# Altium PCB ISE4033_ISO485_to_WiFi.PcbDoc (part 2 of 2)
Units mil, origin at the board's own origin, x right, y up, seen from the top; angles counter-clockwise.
Board outline 4100 x 3450 mil, 4 copper layers (Top Layer, Signal Layer 1, Signal Layer 2, Bottom Layer), stack 52.6 mil thick; 125 components, 68 nets, 339 pads, 551 vias.
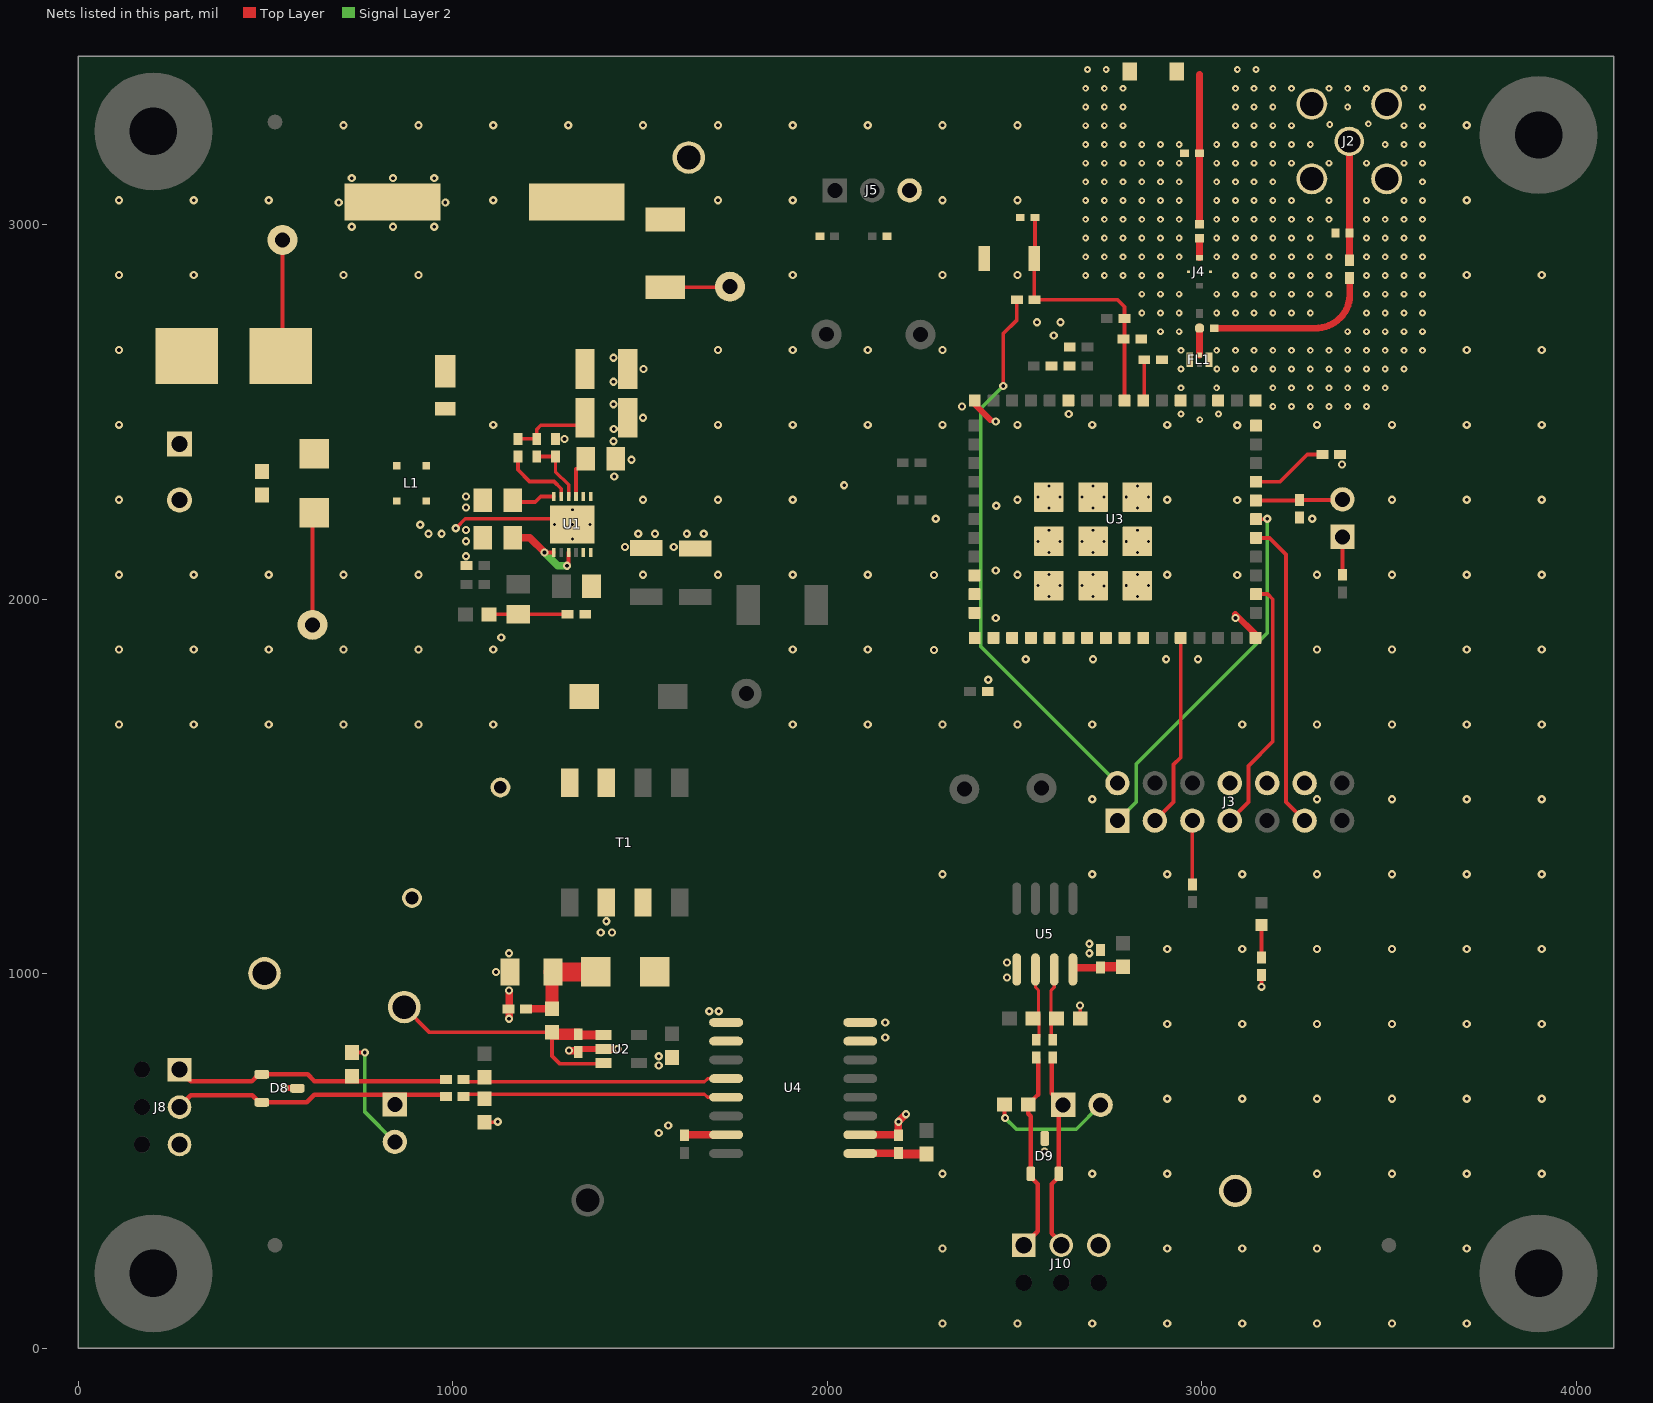
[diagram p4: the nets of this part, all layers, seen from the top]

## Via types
v1: diameter 22, hole 10, Top Layer to Bottom Layer, tented both sides, 276 vias
v2: diameter 18, hole 8, Top Layer to Bottom Layer, tented both sides, 233 vias
v3: diameter 19.68, hole 7.87, Top Layer to Bottom Layer, 41 vias
v4: diameter 22, hole 10, Top Layer to Bottom Layer, 1 vias

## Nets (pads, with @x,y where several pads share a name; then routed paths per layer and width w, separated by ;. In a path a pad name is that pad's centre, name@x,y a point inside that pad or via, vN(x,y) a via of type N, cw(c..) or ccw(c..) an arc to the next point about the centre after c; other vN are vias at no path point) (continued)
GND: C2.2 C3.2 C4.2 C5.2 C6.2 C10.2 C11.2 C12.2 C14.2 C18.1 C18.2 C19.2 C20.2 C21.2 C22.2 C23.1 C25.1 D4.2 D6.2 D7.2 D9.3 E1.1 E1.2 FL1.2 FL1.4 J2.2 J2.3 J2.4 J2.5 J3.8 J3.10 J3.12 J4.3 J4.4 J5.3 J10.3 L1.4 L3.1 L4.2 R7.1 R9.1 R18.1 R21.1 R22.1 R23.1 R24.1 R34.1 S1.2 TP5.1 TP6.1 U1.1 U1.2 U1.13 U3.1 U3.2 U3.16 U3.27 U3.28 U3.30 U3.32 U3.38 U3.43 U3.55 U3.56 U3.57 U3.58 U3.59 U3.60 U3.61 U3.62 U3.63 U4.2 U4.7 U4.8 U5.5 | length 1117.1
  Top Layer w10: v4(1008,2190) 1033,2215 1304,2215 v3(1319,2200) ; C23.1@2183.62,570 C23.1@2190,563.62 ; U3.43@2393.92,2521.08 U3.43@2393.92,2530.96 ; v1(2675,915) 2675.5,914.5 R34.1@2675.5,880 ; 2994.51,3402 2997.51,3405 ; 2995.9,3394.39 2996.51,3395 ; U3.16@3143.92,1897.1 U3.16@3143.92,1906.08 ; v1(3160,965) R21.1@3160,996.38
  Top Layer w17: U3.43@2393.92,2521.08 2435,2480 ; v1@3090,1960 U3.16@3143.92,1906.08
  Top Layer w18: L4.2@2994.12,3001.7 2994.12,3396.61 ; 2994.12,3401.61 2994.51,3402
  Top Layer w20: U4.2@2088.13,570 C23.1@2183.62,570 ; C23.1@2190,568.62 v1(2190,605) v1(2210,625)
  other v1: 2308,66 2508,66 2708,66 2908,66 3108,66 3308,66 3508,66 3708,66 2308,266 2908,266 3108,266 3308,266 3708,266 2308,466 2708,466 2908,466 3308,466 3508,466 3708,466 3908,466 2580,525 2908,666 3108,666 3308,666 3508,666 3708,666 3908,666 2155,830 2908,866 3108,866 3308,866 3508,866 3708,866 3908,866 2155,870 2480,990 2480,1030 2700,1055 2908,1066 3108,1066 3308,1066 3508,1066 3708,1066 3908,1066 2700,1080 2308,1266 2708,1266 2908,1266 3108,1266 3308,1266 3508,1266 3708,1266 3908,1266 2708,1466 3308,1466 3508,1466 3708,1466 3908,1466 108,1666 308,1666 508,1666 708,1666 908,1666 1108,1666 1908,1666 2108,1666 2308,1666 2508,1666 2708,1666 3108,1666 3308,1666 3508,1666 3708,1666 3908,1666 2430,1785 2530,1840 2710,1840 2905,1840 2990,1840 2285,1865 108,1866 308,1866 508,1866 708,1866 908,1866 1108,1866 1908,1866 2108,1866 3308,1866 3508,1866 3708,1866 3908,1866 1129,1898 2450,1950 3090,1950 2285,2065 3095,2065 108,2066 308,2066 508,2066 708,2066 908,2066 1508,2066 1708,2066 1908,2066 2108,2066 2508,2066 2908,2066 3308,2066 3508,2066 3708,2066 3908,2066 2450,2077 1035,2115 1460,2140 1590,2140 1035,2155 935,2175 970,2175 1495,2175 1540,2175 1625,2175 1670,2175 1035,2185 913,2199 2290,2215 3295,2215 1035,2245 2451,2250 3095,2265 108,2266 1508,2266 1708,2266 1908,2266 2508,2266 2908,2266 3508,2266 3708,2266 3908,2266 1035,2275 2045,2305 1431,2328 3375,2360 1477,2373 1429,2422 1298,2428 1430,2455 3095,2465 108,2466 1108,2466 1708,2466 1908,2466 2108,2466 2308,2466 2508,2466 2708,2466 2908,2466 3308,2466 3508,2466 3708,2466 3908,2466 2450,2475 1508,2485 2645,2495 2360,2515 1429,2521 1429,2581 1509,2615 1429,2645 108,2666 1708,2666 1908,2666 2108,2666 2308,2666 3708,2666 3908,2666 2605,2705 2560,2740 2623,2740 108,2866 308,2866 708,2866 908,2866 1908,2866 2308,2866 2508,2866 3708,2866 3908,2866 730,2995 840,2995 950,2995 695,3060 980,3060 108,3066 308,3066 508,3066 1108,3066 1708,3066 1908,3066 2308,3066 2508,3066 3708,3066 730,3125 840,3125 950,3125 708,3266 908,3266 1108,3266 1308,3266 1508,3266 1708,3266 1908,3266 2108,3266 2308,3266 2508,3266 3708,3266
  other v2: 2995,2480 2945,2495 3045,2495 3190,2515 3240,2515 3290,2515 3340,2515 3390,2515 3440,2515 2945,2565 3040,2565 3190,2565 3240,2565 3290,2565 3340,2565 3390,2565 3440,2565 3490,2565 2945,2615 3040.26,2615 3090,2615 3140,2615 3190,2615 3240,2615 3290,2615 3340,2615 3390,2615 3440,2615 3490,2615 3540,2615 2945,2665 3040,2665 3090,2665 3140,2665 3190,2665 3240,2665 3290,2665 3340,2665 3390,2665 3440,2665 3490,2665 3540,2665 3590,2665 2890,2715 2940,2715 3390,2715 3440,2715 3490,2715 3540,2715 3590,2715 2840,2765 2890,2765 2940,2765 3040,2765 3090,2765 3140,2765 3190,2765 3240,2765 3290,2765 3440,2765 3490,2765 3540,2765 3590,2765 2840,2815 2890,2815 2940,2815 3040,2815 3090,2815 3140,2815 3190,2815 3240,2815 3290,2815 3340,2815 3440,2815 3490,2815 3540,2815 3590,2815 2690,2865 2740,2865 2790,2865 2840,2865 2890,2865 3090,2865 3140,2865 3190,2865 3240,2865 3290,2865 3340,2865 3440,2865 3490,2865 3540,2865 3590,2865 2690,2915 2740,2915 2790,2915 2840,2915 2890,2915 2940,2915 3040,2915 3090,2915 3140,2915 3190,2915 3240,2915 3290,2915 3340,2915 3440,2915 3490,2915 3540,2915 3590,2915 2690,2965 2740,2965 2790,2965 2840,2965 2890,2965 2940,2965 3040,2965 3090,2965 3140,2965 3190,2965 3240,2965 3290,2965 3440,2965 3490,2965 3540,2965 3590,2965 2690,3015 2740,3015 2790,3015 2840,3015 2890,3015 2940,3015 3040,3015 3090,3015 3140,3015 3190,3015 3240,3015 3290,3015 3340,3015 3440,3015 3490,3015 3540,3015 3590,3015 2690,3065 2740,3065 2790,3065 2840,3065 2890,3065 2940,3065 3040,3065 3090,3065 3140,3065 3190,3065 3240,3065 3340,3065 3440,3065 3540,3065 3590,3065 2690,3115 2740,3115 2790,3115 2840,3115 2890,3115 2940,3115 3040,3115 3090,3115 3140,3115 3190,3115 3590,3115 2690,3165 2740,3165 2790,3165 2840,3165 2890,3165 2940,3165 3040,3165 3090,3165 3140,3165 3190,3165 3240,3165 3340,3165 3440,3165 3540,3165 3590,3165 2690,3215 2740,3215 2790,3215 2840,3215 2890,3215 2940,3215 3040,3215 3090,3215 3140,3215 3190,3215 3240,3215 3290,3215 3490,3215 3540,3215 3590,3215 2690,3265 2740,3265 2790,3265 3090,3265 3140,3265 3190,3265 3240,3265 3540,3265 3590,3265 3342,3268 3445,3270 2690,3315 2740,3315 2790,3315 3090,3315 3140,3315 3190,3315 3390,3315 3590,3315 2690,3365 2740,3365 2790,3365 3090,3365 3140,3365 3190,3365 3240,3365 3340,3365 3390,3365 3440,3365 3540,3365 3590,3365 2695,3415 2745,3415 3095,3415 3145,3415
  other v3: 2591.76,2007.34 2709.87,2007.34 2827.98,2007.34 2739.39,2035.88 2562.23,2036.87 2621.28,2036.87 2680.34,2036.87 2798.45,2036.87 2857.5,2036.87 2591.76,2066.39 2709.87,2066.39 2827.98,2066.39 2591.76,2125.45 2709.87,2125.45 2827.98,2125.45 2739.39,2153.99 2562.23,2154.98 2621.28,2154.98 2680.34,2154.98 2798.45,2154.98 2857.5,2154.98 1319,2160.63 2591.76,2184.5 2709.87,2184.5 2827.98,2184.5 1271.76,2200 1366.24,2200 1319,2239.37 2591.76,2243.56 2709.87,2243.56 2827.98,2243.56 2562.23,2273.09 2621.28,2273.09 2680.34,2273.09 2739.39,2273.09 2798.45,2273.09 2857.5,2273.09 2591.76,2302.61 2709.87,2302.61 2827.98,2302.61
GPIO7: U3.52
GPIO8: U3.53
GPIO9: U3.54
GPIO10: U3.3
GPIO11: U3.4
GPIO12: U3.9
GPIO13: U3.10
GPIO14: U3.5
GPIO15: U3.6
GPIO16: U3.7
GPIO17: U3.8
IN1: F1.2 J1.1
IN1_F: C1.1 D1.2 F1.1 L1.2 TP1.1 | length 311.9
  Top Layer w10: F1.1@540.49,2650 545,2654.51 TP1.1@545,2960
IN1_FL: D2.2 L1.1
IN2: C1.2 D1.1 J1.2 L1.3 TP4.1 | length 301.3
  Top Layer w10: TP4.1@625,1932 625,2226.26 D1.1@630,2231.26
ISO485_N: R30.2 R35.1 U4.13 | length 703.3
  Top Layer w8.5: R35.1@1030,678.25 1672.09,678.25 1680.34,670 U4.13@1729.87,670
ISO485_OUT_N: D8.2 J7.1 J8.2 R35.2 | length 743.2
  Top Layer w12: J8.2@270,644 270,645.5 300,675.5 464.5,675.5 483.4,656.6 D8.2@489.76,656.6 610.1,656.6 630,676.5 976.88,676.5 R35.2@981.38,672
ISO485_OUT_P: D8.1 J8.1 R25.2 R29.1 | length 742.4
  Top Layer w12: J8.1@270,744 270,742.5 300,712.5 462.5,712.5 481.4,731.4 D8.1@489.76,731.4 612.1,731.4 630,713.5 976.88,713.5 R25.2@981.38,718
ISO485_P: R25.1 R28.1 U4.12 | length 703.3
  Top Layer w8.5: R25.1@1030,711.75 1672.09,711.75 1680.34,720 U4.12@1729.87,720
ISO_GND: C6.1 C7.2 C15.2 C16.2 C24.1 D8.3 J8.3 R2.1 R30.1 T1.7 TP11.1 U2.2 U4.9 U4.10 U4.15 | length 388.4
  Top Layer w10: D8.3@583.24,695 D8.3@584.24,694 ; R30.1@1085,603.5 1118.5,603.5 v1(1120,605) ; C24.1@1619,568.62 C24.1@1620.38,570
  Top Layer w15: v1(550,695) D8.3@583.24,695 ; C16.2@1330,795 1334,799 U2.2@1402.6,799
  Top Layer w20: v1(1150,880) v1(1150,955) ; v1(1310,795) C16.2@1330,795 ; U2.2@1402.6,799 v1(1440,799) ; C24.1@1620.38,570 U4.15@1729.87,570
  other v1: 1550,575 1575,595 1550,755 1550,780 1685,900 1710,900 1115.51,1005 1150,1055 1395,1110 1425,1110 1410,1140
J4-2: J4.2 L4.1 | length 51.9
  Top Layer w18: J4.2@2994,2912.4 L4.1@2994,2964.3
LDO_IN: C16.1 R10.2 TP12.1 U2.1 U2.3 | length 773.5
  Top Layer w10: TP12.1@870,911 937.5,843.5 R10.2@1265,843.5 ; R10.2@1269.88,838.62 R10.2@1265,843.5 ; C16.1@1335,838.62 C16.1@1337.22,836.4 ; U2.3@1402.6,761.6 1401,760 1285,760 1265,780 R10.2@1265,843.5
  Top Layer w25: C16.1@1337.22,836.4 U2.1@1402.6,836.4
  Top Layer w30: R10.2@1269.88,838.62 C16.1@1335,838.62
NetC23_2: C23.2 R27.1 U4.1 | length 178.6
  Top Layer w10: C23.2@2188.62,520 C23.2@2190,521.38 C23.2@2192.87,518.5
  Top Layer w20: U4.1@2088.13,520 C23.2@2188.62,520
  Top Layer w25: C23.2@2192.87,518.5 R27.1@2265,518.5
NetC25_2: C25.2 R31.1 U5.8 | length 136.9
  Top Layer w10: U5.8@2656,1011.51 U5.8@2660.87,1016.38 ; C25.2@2730,1016.38 C25.2@2732.13,1018.5
  Top Layer w20: U5.8@2660.87,1016.38 C25.2@2730,1016.38
  Top Layer w25: C25.2@2732.13,1018.5 R31.1@2790,1018.5
NetD3_2: D3.2 T1.6
NetD5_2: D5.2 R21.2 | length 86.9
  Top Layer w10: R21.2@3160,1043.62 D5.2@3160,1130.47
NetJ3_5: J3.5 R14.1 | length 155.4
  Top Layer w10: R14.1@2975,1253.62 J3.5@2975,1409
NetJ6_1: J6.1 R20.1 | length 101.4
  Top Layer w10: R20.1@3375.92,2065.65 J6.1@3375.92,2167.03
NetJ7_2: J7.2 R29.2 | length 306.3
  Top Layer w10: R29.2@731,789.5 764.5,789.5 v1(765,790)
  Signal Layer 2 w10: v1(765,790) 765,631 J7.2@845,551
NetJ9_2: J9.2 R33.2 | length 331
  Top Layer w10: R33.2@2473.5,651 2473.5,616.5 v1(2475,615)
  Signal Layer 2 w10: v1(2475,615) 2505,585 2665,585 J9.2@2730,650
NetR3_2: R3.2 U1.5 | length 192.5
  Top Layer w10: R3.2@1174,2381.38 1174,2346 1205,2315 1270,2315 1289.47,2295.53 U1.5@1289.47,2274.8
NRST: C22.1 D4.1 R12.1 R19.1 S1.1 U3.35 | length 721.2
  Top Layer w10: D4.1@2554.68,3020 2554.68,2911.87 S1.1@2552.85,2910.03 2552.85,2800.77 R12.1@2553.62,2800 2775,2800 2793.62,2781.38 R19.1@2793.62,2750 2793.62,2697.24 C22.1@2791.38,2695 2793.92,2692.46 U3.35@2793.92,2530.96
NTRST: J3.2 R12.2 | length 1482.1
  Top Layer w10: v1(2470,2570) 2470,2710 2506.38,2746.38 R12.2@2506.38,2800
  Signal Layer 2 w10: v1(2470,2570) 2410,2510 2410,1874 J3.2@2775,1509
PS_VIN: C3.1 C4.1 C5.1 R1.2 R3.1 R5.2 TP2.1 U1.3 | length 465.5
  Top Layer w10: R3.1@1174,2428.62 R5.2@1224,2428.62 1224,2454 1235,2465 1332.91,2465 C4.1@1352.91,2485 ; U1.3@1328.84,2274.8 1328.84,2347.84 1330,2349 ; R1.2@1567,2833.45 1738.45,2833.45 TP2.1@1740,2835
RF_FL_O: FL1.3 R13.1 R15.2 | length 74.5
  Top Layer w18: FL1.3@2994,2652.8 R15.2@2994,2727.31
RIP_INJ: C9.2 C13.1 R6.2 | length 209.9
  Top Layer w10: C9.2@1096.5,1960 C13.1@1175,1960 R6.2@1306.38,1960
RS485_N: R34.2 R37.1 U5.7 | length 177.2
  Top Layer w8.5: R34.2@2597,893 2597.75,893.75 2597.75,955.7 2606,963.95 U5.7@2606,1011.51 ; R37.1@2598,831 2598,865.5 R34.2@2612.5,880
RS485_OUT_N: D9.2 J9.1 J10.2 R37.2 | length 537
  Top Layer w12: R37.2@2600,776.38 2600,680 J9.1@2630,650 2618.4,638.4 D9.2@2618.4,465.76 2618.4,457.4 2599.5,438.5 2599.5,306.5 2625,281 J10.2@2625,275
RS485_OUT_P: D9.1 J10.1 R33.1 R36.2 | length 540.7
  Top Layer w12: J10.1@2525,275 2562.5,312.5 2562.5,438.5 2543.6,457.4 D9.1@2543.6,465.76 2543.6,619.2 2536.5,626.3 R33.1@2536.5,651 2563,677.5 2563,771.38 R36.2@2558,776.38
RS485_P: R32.1 R36.1 U5.6 | length 210.1
  Top Layer w8.5: R32.1@2549.5,880 R32.1@2565.5,864 ; U5.6@2556,1011.51 2556,963.95 2564.25,955.7 2564.25,894.12 2565.5,892.87 R32.1@2565.5,864 ; R36.1@2563,829 2565.5,831.5 R32.1@2565.5,864
SMA_LEG: C17.2 R13.2 | length 445.3
  Top Layer w18: R13.2@3041.62,2724 3302.78,2724 ccw(c3302.78,2819.6) 3370.38,2752 ccw(c3310.02,2812.36) 3395.38,2812.36 C17.2@3395.38,2854.38
SMA_OUT: C17.1 J2.1 L3.2 | length 318.4
  Top Layer w18: J2.1@3393,3223 3394.7,3221.3 L3.2@3394.7,2978 ; C17.1@3395,2905.62 L3.2@3395,2978.3
SOP0: R22.2 U3.34 | length 110.1
  Top Layer w10: U3.34@2843.92,2530.96 2846.38,2533.42 R22.2@2846.38,2640
SOP1: R23.2 U3.24 | length 207.6
  Top Layer w10: U3.24@3144.91,2314.03 3209.03,2314.03 3282.03,2387.03 R23.2@3322.3,2387.03
SOP2: J6.2 R24.2 U3.23 | length 232.3
  Top Layer w10: U3.23@3144.91,2264.03 3259.3,2264.03 R24.2@3260.92,2265.65 3374.54,2265.65 J6.2@3375.92,2267.03
SS: C14.1 U1.6 | length 116.9
  Top Layer w10: C14.1@1159,2260 1220,2260 1234.8,2274.8 U1.6@1269.79,2274.8
SW: C8.1 L2.1 R6.1 T1.1 T1.2 U1.11 U1.12
TCK: J3.11 U3.21 | length 830
  Top Layer w10: U3.21@3144.91,2164.03 3180.97,2164.03 3225,2120 3225,1459 J3.11@3275,1409
TDI: J3.3 U3.12 | length 516.7
  Top Layer w10: J3.3@2875,1409 2925,1459 2925,1559 2943.92,1577.92 U3.12@2943.92,1897.1
TDO: J3.7 U3.18 | length 689.5
  Top Layer w10: J3.7@3075,1409 3125,1459 3125,1555 3190,1620 3190,2000 3175.97,2014.03 U3.18@3144.91,2014.03
TMS: J3.1 U3.22 | length 1002.2
  Top Layer w10: U3.22@3144.91,2214.03 3174.03,2214.03 v1(3175,2215)
  Signal Layer 2 w10: J3.1@2775,1409 2825,1459 2825,1560 3175,1910 v1(3175,2215)
UVLO: R5.1 R7.2 U1.4 | length 171.1
  Top Layer w9: R7.2@1274,2381.38 1274,2341 1309.16,2305.84 U1.4@1309.16,2274.8
  Top Layer w10: R5.1@1224,2381.38 R7.2@1274,2381.38
V_SEC_RECT: C7.1 D3.1 R2.2 R10.1 | length 283.1
  Top Layer w10: R2.2@1195.62,906 R2.2@1196.12,906.5 ; C7.1@1265,1002.91 C7.1@1267.09,1005
  Top Layer w20: R2.2@1196.12,906.5 R10.1@1265,906.5
  Top Layer w35: R10.1@1265,906.5 C7.1@1265,1002.91
  Top Layer w50: C7.1@1267.09,1005 D3.1@1381.26,1005
VCC_REG: C12.1 U1.7 U1.9 | length 241
  Top Layer w10: v1(1245,2125) 1245.2,2125.2 U1.7@1269.79,2125.2 ; v1(1305,2090) 1309.16,2094.16 U1.9@1309.16,2125.2
  Top Layer w20: C12.1@1159,2170 1164,2165 1205.39,2165 v1@1245.2,2125.2
  Signal Layer 2 w20: v1(1245,2125) 1280,2090 v1(1305,2090)
VIN_FLT: C2.1 D2.1 R1.1
pads on no net: FID1.1 FID2.1 FID3.1 H1.1 H2.1 H3.1 H4.1 J3.4 J3.6 J3.9 J3.13 J3.14 J8.4 J8.5 J8.6 J10.4 J10.5 J10.6 T1.5 T1.8 U2.4 U3.11 U3.13 U3.14 U3.15 U3.17 U3.19 U3.20 U3.25 U3.26 U3.29 U3.33 U3.39 U3.41 U3.42 U3.44 U3.45 U3.51 U4.11 U4.14

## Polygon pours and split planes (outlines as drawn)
VIN_FLT on Top Layer "Top Layer-No Net" (solid, remove dead copper, pour order 43): 915,2565 915,2780 915,2825 1200,3110 1545,3110 1620,3110 1620,2965 1410,2965 1010,2565
PS_VIN on Top Layer "Top Layer-No Net" (solid, remove dead copper, pour order 41): 1620,2870 1470,2870 1455,2870 1325,2740 1325,2265 1335,2265 1335,2295 1335,2300 1345,2310 1385,2350 1385,2360 1385,2460 1385,2670 1490,2775 1495,2780 1535,2780 1620,2780
SW on Top Layer "Top Layer-No Net" (solid, remove dead copper, pour order 42): 1340,1960 1340,1935 1330,1925 1275,1870 1275,1475 1440,1475 1440,1570 1440,2050 1395,2095 1380,2095 1340,2055 1340,2050 1340,1990
GND on Top Layer "Top Layer-No Net" (solid, remove dead copper, pour order 44): 2648.19,3508.63 2648.19,2808.63 2748.19,2808.63 2848.19,2708.63 2848.19,2508.63 3348.19,2508.63 3448.19,2508.63 3648.19,2708.63 3648.19,3508.63
GND on Top Layer "Top Layer-No Net" (solid, remove dead copper, pour order 46): 25,3425 4075,3425 4075,25 2100,25 2100,1475 25,1475
3V3_ISO on Signal Layer 2 "Top Layer-No Net" (solid, remove dead copper, pour order 49): 1600,870 1600,585 1550,535 1550,505 1595,505 1630,540 1650,560 1650,870
3V3 on Signal Layer 2 "Top Layer-No Net" (solid, remove dead copper, pour order 50): 2015,2270 2080,2270 2115,2295 2115,2425 2150,2460 2365,2675 2629,2675 2679,2725 2740,2725 2740,2600 2515,2600 2410,2600 2385,2575 2220,2410 2220,2320 2220,840 2260,800 2325,735 2325,610 2325,545 2270,545 2270,695 2250,715 2155,810 2155,830 2155,2125 2100,2180 2005,2180 2005,2270
ISO_GND on Signal Layer 1 "Top Layer-No Net" (solid, remove dead copper, pour order 47): 25,1225 1725,1225 1725,25 25,25
GND on Signal Layer 1 "Top Layer-No Net" (solid, remove dead copper, pour order 48): 25.63,3423.22 4075.63,3423.22 4075.63,23.22 2100,23.22 2100,1475 25.63,1475
GND on Bottom Layer "Top Layer-No Net" (solid, remove dead copper, pour order 51): 2648.19,3508.63 2648.19,2808.63 2748.19,2808.63 2848.19,2708.63 2848.19,2508.63 3348.19,2508.63 3448.19,2508.63 3648.19,2708.63 3648.19,3508.63
GND on Bottom Layer "Top Layer-No Net" (solid, remove dead copper, pour order 53): 25,3425 4075,3425 4075,25 2100,25 2100,1475 25,1475

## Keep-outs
Keep-Out Layer:
  lines w10: -5,0 ccw(c0,0) 0,-5 ; -5,0 ccw(c0,0) 0,-5 ; -5,0 -5,3450 ; -5,3450 cw(c0,3450) 0,3455 ; -5,3450 cw(c0,3450) 0,3455 ; 0,-5 4100,-5 ; 0,3455 4100,3455 ; 4100,-5 ccw(c4100,0) 4105,0 ; 4100,-5 ccw(c4100,0) 4105,0 ; 4100,3455 cw(c4100,3450) 4105,3450 ; 4100,3455 cw(c4100,3450) 4105,3450 ; 4105,0 4105,3450
  text ".Layer_Name" at 577,-858.49 h60

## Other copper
Top Layer:
  rectangle net GND: 1344,2242 1375,2291
  rectangle net IN1: 160,2370 380,2725
  rectangle net IN1_F: 455,2327.72 864.41,2725
  rectangle net IN2: 160,2120 865,2295
  rectangle net IN1_FL: 908,2325 1015,2530
  rectangle net SW: 1344,1920 1403,2137
  rectangle net 3V3_OUT: 1470,1475 1830,2035
  rectangle net NetD3_2: 1485,965 1535,1230
  rectangle net NetD3_2: 1500,965 1580,1115
  rectangle net 3V3_ISO: 1475,815 1650,870
  rectangle net 3V3_ISO: 1550,505 1625,535
  rectangle net ISO_GND: 1380,1095 1440,1230
  rectangle net ISO_GND: 1535,555 1630,605
  rectangle net ISO_GND: 1540,745 1610,795
  rectangle net ISO_GND: 1670,810 1725,915
  rectangle net ISO_GND: 1100,940 1180,1070
  rectangle net 3V3: 2245,555 2315,605
  rectangle net 3V3: 2505,2610 2565,2665
  rectangle net 3V3: 2679,2515 2759,2725
  rectangle net 3V3: 2529,2520 2559,2625
  rectangle net 3V3: 1940,1900 2035,2275
  rectangle net 3V3: 2000,2180 2080,2270
  rectangle net 3V3: 2770,1060 2825,1145
  region net GND: 3050.5,3435 2919.5,3435 2919.5,3385 3050.5,3385
  rectangle net GND: 2100,810 2150,875
  rectangle net GND: 2690,1045 2745,1090
  rectangle net GND: 2470,975 2515,1045
  region net GND: 2982,3181 2993,3170 2995,3170 3005.5,3180.5 3005.5,3188.5 2982,3189
  pour cut-out: 135,2750 450,2749.02 450,2735 445,2740 450,2735 450,2295 134.51,2295
  pour cut-out: 865,2725 915,2725 915,2250 865,2200
  region net GND: 3006,3201.5 2995,3212.5 2993,3212.5 2982.5,3202 2982.5,3194 3006,3193.5
  region net CC_RF_OUT: 3009,2548 2996,2562 2992,2562 2978,2548 2978,2544 3009,2544
  pour cut-out: 2966,3257 3022,3257 3022,2959 3022,2657 2966,2657
  pour cut-out: 2806,3241 3043.01,3241 3043.01,3444 2806,3444
  region net GND: 2980,3387 2993,3374 2997,3374 3011,3388 3011,3392 2980,3392
  text ".Layer_Name" at 577,-858.49 h60
Signal Layer 1:
  pour cut-out: 2806,3241 3043.01,3241 3043.01,3444 2806,3444
  text ".Layer_Name" at 577,-858.49 h60
Signal Layer 2:
  rectangle net 3V3: 2215,1100 2825,1145
  text ".Layer_Name" at 577,-858.49 h60
Bottom Layer:
  pour cut-out: 2806,3241 3043.01,3241 3043.01,3444 2806,3444
  text ".Layer_Name" at 577,-858.49 h60

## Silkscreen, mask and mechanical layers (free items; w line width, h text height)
Top Overlay:
  circle w10: c1235,1515 r5
  circle w10: c2125,480 r5
  lines w8: 30,2235 50,2255 ; 35,2255 100,2255 ; 50,2235 70,2255 70,2290 ; 70,2235 90,2255
  lines w10: 20.28,2415 ccw(c42.64,2415) 65,2415 cw(c87.36,2415) 109.72,2415
  text "HEADER" at 2220,3350 h50 r180
  text "PROGRAMMING" at 2300,3290 h50 r180
  text "TX" at 2053,3230 h60 r180
  text "RX" at 2155,3230 h60 r180
  text "GND" at 2300,3230 h60 r180
  text "GND" at 1730,3170 h60
  text "DC INPUT" at 1645,2700 h60
  text "TX" at 1957,2580 h60
  text "RX" at 2215,2580 h60
  text "+3.3V" at 1726,1636 h60
  text "485_TX" at 2277,1385 h60
  text "485_RX" at 2488,1384 h60
  text ".PCB_Rev" at 3743,1206 h105 r90
  text "ISO_GND" at 395,880 h60
  text "+" at 56,754 h40 r270
  text "-" at 56,655 h40 r270
  text ".PRJ_Number" at 3743,606 h105 r90
  text ".TID" at 3833,606 h105 r90
  text "GND" at 57,585 h40 r270
  text "GND" at 3040,280 h60
  text "+3.3V ISOLATED" at 1175,260 h60
  text ".CopyrightYear" at 532,90 h105
  text "TI" at 808,90 h105
  text "©" at 415,86.48 h105
  text "GND" at 2691,63 h40
  text "-" at 2621,59 h40
  text "+" at 2524,58 h40
  text ".Layer_Name" at 577,-858.49 h60
  text "+3.3V ISOLATED" at 350,-2020 h40
Bottom Overlay:
  text ".Layer_Name" at 577,-858.49 h60
Top Paste:
  text ".Layer_Name" at 577,-858.49 h60
Bottom Paste:
  text ".Layer_Name" at 577,-858.49 h60
Top Solder:
  text ".Layer_Name" at 577,-858.49 h60
  text ".Layer_Name" at 577,-858.49 h60
Bottom Solder:
  text ".Layer_Name" at 577,-858.49 h60
Drill Guide:
  text ".Layer_Name" at 577,-858.49 h60
M1 Board Outline:
  lines w7: 770,1330 770,1370 1770,1370 1770,1330 770,1330 ; 1890,370 1890,1020 1930,1020 1930,370 1890,370
  lines w10: 0,0 4100,0 4100,3450 0,3450 0,0
  text ".Layer_Name" at 577,-858.49 h60
M2 Board Dimensions:
  rectangle: 125,-400 500,-275
  rectangle: 0,-275 125,-150
  lines w7: 0,-275 1000,-275 ; 125,-400 125,-150 ; 250,-400 250,-150 ; 500,-400 500,-150 ; 750,-400 750,-150 ; 0,-400 0,-150 1000,-150 1000,-400 0,-400
  text ".Layer_Name" at 577,-858.49 h60
M3 3D STEP Top:
  text ".Layer_Name" at 577,-858.49 h60
M4 3D STEP Bottom:
  text ".Layer_Name" at 577,-858.49 h60
M5 Assembly Top:
  lines w10: -292,-930.17 6308,-930.17 ; -292,-726.83 6310,-726.83 ; -292,-523.5 -292,-1133.5 3713,-1133.5 6310,-1133.5 6310,-523.5 -291.5,-523.5 -291.5,-1133.5 1284,-1133.5 ; 2173,-1133.5 2173,-523.5 ; 3440,-726.83 3440,-523.5 ; 4280,-726.83 4280,-523.5 ; 4902,-1140 4902,-937.17
  text "COMPONENTS MARKED 'DNP' SHOULD NOT BE POPULATED." at 1153.5,-318.5 h60
  text "ASSEMBLY VARIANT:" at 1153,-434 h60
  text ".VariantName" at 2189,-434 h60
  text "PCB VIEWED FROM TOP SIDE" at -228.5,-655.67 h60
  text "BOARD #:" at 2248,-655.67 h60
  text ".PRJ_Number" at 2793.5,-655.67 h60
  text "REV:" at 3638,-655.67 h60
  text ".PCB_Rev" at 3929.5,-655.67 h60
  text "SVN REV:" at 4476,-655.67 h60
  text ".VersionControl_RevNumber" at 4982,-655.67 h60
  text "TID #:" at 2248,-879 h60
  text ".TID" at 2793.5,-879 h60
  text "PLOT NAME =" at -228.5,-1064.34 h60
  text ".plot_File_Name" at 577,-1064.34 h60
  text "GENERATED    :" at 2250,-1064.34 h60
  text ".Print_Date" at 3119.5,-1064.34 h60
  text ".Print_Time" at 3848.5,-1064.34 h60
  text "TEXAS INSTRUMENTS" at 5113,-1064.34 h60
M6 Assembly Bottom:
  lines w10: -292.5,-727.33 6309.5,-727.33 ; -290.5,-930.67 6309.5,-930.67 ; 1115.5,-1140.5 1115.5,-937.67 ; 1737.5,-727.33 1737.5,-524 ; 2577.5,-727.33 2577.5,-524 ; 3844.5,-1134 3844.5,-524 ; 4733.5,-1134 6309,-1134 6309,-524 -292.5,-524 -292.5,-1134 2304.5,-1134 6309.5,-1134 6309.5,-524
  text "COMPONENTS MARKED 'DNP' SHOULD NOT BE POPULATED." at 6102,-318 h60
  text ".VariantName" at 5058,-434 h60
  text "ASSEMBLY VARIANT:" at 6097,-434 h60
  text ".VersionControl_RevNumber" at 1035.5,-656.17 h60
  text "SVN REV:" at 1541.5,-656.17 h60
  text ".PCB_Rev" at 2088,-656.17 h60
  text "REV:" at 2379.5,-656.17 h60
  text ".PRJ_Number" at 3224,-656.17 h60
  text "BOARD #:" at 3769.5,-656.17 h60
  text "PCB VIEWED FROM BOTTOM SIDE" at 6246,-656.17 h60
  text ".TID" at 3224,-879.5 h60
  text "TID #:" at 3769.5,-879.5 h60
  text "TEXAS INSTRUMENTS" at 904.5,-1064.84 h60
  text ".Print_Time" at 2169,-1064.84 h60
  text ".Print_Date" at 2898,-1064.84 h60
  text "GENERATED    :" at 3767.5,-1064.84 h60
  text ".plot_File_Name" at 5440.5,-1064.84 h60
  text "PLOT NAME =" at 6246,-1064.84 h60
M9 Title Sheet:
  drawing of 57 lines, arcs and shapes, not listed
  text "1" at 739.84,8036.5 h70
  text "2" at 3235.5,8036.5 h70
  text "3" at 5724.84,8036.5 h70
  text "4" at 8231.51,8036.5 h70
  text "5" at 10730.5,8036.5 h70
  text "6" at 13235.5,8036.5 h70
  text "A" at -416.5,6893.5 h70
  text "A" at 14383.5,6893.5 h70
  text "B" at -416.5,4513.5 h70
  text "B" at 14383.5,4513.5 h70
  text "C" at -416.5,2138.5 h70
  text "C" at 14383.5,2138.5 h70
  text "PROJECT TITLE:" at 11343.5,277.5 h45
  text ".PRJ_Title" at 11393.5,144.17 h70
  text "DESIGNED FOR:" at 11343.5,-23.5 h45
  text ".PRJ_Customer" at 11393.5,-163.5 h70
  text "D" at -416.5,-231.5 h70
  text "D" at 14383.5,-231.5 h70
  text "FILE NAME:" at 11343.5,-323.5 h45
  text ".PCB_File_Name_No_Path" at 11393.5,-443.5 h70
  text "Texas Instruments (TI) and/or its licensors do not warrant the accuracy or completeness of this specification" at 6374,-605.34 h45
  text "ENGINEER:" at 11343.5,-613.5 h45
  text "LAYOUT BY:" at 12848.5,-613.5 h45
  text "or any information contained therein. TI and/or its licensors do not warrant that this design will meet" at 6329.01,-718 h45
  text ".PRJ_Engineer" at 11393.5,-768.49 h70
  text ".PCB_Layout" at 12899,-768.49 h70
  text "the specifications, will be suitable for your application or fit for any particular purpose, or will operate in" at 6329.01,-830.67 h45
  text ".Layer_Name" at 577,-858.49 h60
  text "ALTIUM DESIGNER VERSION:" at 12848.5,-923.5 h45
  text "an implementation. TI and/or its licensors do not warrant that the design is production worthy. You should" at 6329.01,-943.33 h45
  text "completely validate and test your design implementation to confirm the system functionality for your application." at 6374,-1056 h45
  text ".print_Scale" at 11393.5,-1056.83 h70
  text ".Application_BuildNumber" at 12899,-1056.83 h70
  text "1" at 739.84,-1263.5 h70
  text "2" at 3235.5,-1263.5 h70
  text "3" at 5724.84,-1263.5 h70
  text "4" at 8231.51,-1263.5 h70
  text "5" at 10730.5,-1263.5 h70
  text "6" at 13235.5,-1263.5 h70
M10 Fab Notes:
  drawing of 185 lines, arcs and shapes, not listed
  text "IMPEDANCE CONTROLS:" at 8061.46,6005 h60
  text "DESIGN INFORMATION" at 12381.02,5910 h60
  text "120 OHM DIFF, TOP SIDE, USING 12 MIL TRACES WITH 25 MIL SPACING" at 8185,5885 h60
  text "140 OHM DIFF, TOP SIDE, USING 8.5MIL TRACES WITH 25 MIL SPACING" at 8180,5765 h60
  text "MIN. TRACK WIDTH:" at 11736.46,5730 h60
  text "8" at 12832.7,5730 h60
  text "MIL" at 12987.46,5730 h60
  text "50 OHM SE, TOP SIDE, USING 18MIL TRACE" at 8180,5655 h60
  text "MIN. CLEARANCE:" at 11736.46,5598 h60
  text "7.6" at 12772.7,5598 h60
  text "MIL" at 12987.46,5598 h60
  text "MIN. VIA PAD SIZE:" at 11736.46,5466 h60
  text "18" at 12802.71,5466 h60
  text "MIL" at 12987.46,5466 h60
  text "0.05mm (2MIL)" at 12431.46,5324.29 h60
  text "MINIMUM ANNULAR RING" at 11407.23,5320 h60
  text "EXTERNAL" at 13139.46,5320 h60
  text "PER" at 11607.23,5202 h60
  text "IPC-D-275 CLASS 2 LEVEL C" at 11827.23,5202 h60
  text "MIL, HOLES" at 13315.46,5089.71 h60
  text "+/-" at 12923,5089 h60
  text "+/-" at 13777,5089 h60
  text "REGISTRATION TOLERANCES:" at 11407.23,5084 h60
  text "METAL" at 12607,5084 h60
  text "5" at 13183.2,5084 h60
  text "3" at 14016.2,5084 h60
  text "MIL" at 14132.46,5084 h60
  text "MATERIAL:" at 11332.46,4874.54 h60
  text "FR-4 High Tg" at 12318.9,4734.21 h60
  text "FR-408" at 11753.46,4725.64 h60
  text "X" at 12165.46,4725.64 h60
  text "OTHER" at 13241.46,4725.64 h60
  text "62 MIL (1.6mm) +/-10%" at 12073.56,4562.92 h60
  text "X" at 13235,4560 h60
  text "53MIL +/-10%" at 13665,4560 h60
  text "THICKNESS:" at 11407.23,4558.64 h60
  text "OTHER" at 13358.46,4558.64 h60
  text "TOLERANCE:" at 11407.23,4400.64 h60
  text "X" at 12246.53,4400.64 h60
  text "ANSI IPC-6012 TYPE 3 CLASS 2" at 12433.48,4400.64 h60
  text "OTHER +/-" at 12433.46,4244.64 h60
  text "BOW & TWIST:" at 11407.23,4087.64 h60
  text "X" at 12246.53,4087.64 h60
  text "ANSI IPC-6012 TYPE 3 CLASS 2" at 12433.48,4087.64 h60
  text "OTHER +/-" at 12433.46,3929.13 h60
  text "DRILLING:" at 11332.46,3790.64 h60
  text "REFERENCE:" at 11407.23,3673.64 h60
  text "X" at 12055.46,3673.64 h60
  text "AS SHOWN" at 12242.46,3673.64 h60
  text "X" at 12956.46,3673.64 h60
  text "NC_DRILL FILES" at 13093.46,3673.64 h60
  text "PTH MIN COPPER THICKNESS:" at 11407.23,3515.64 h60
  text "X" at 12757.46,3515.64 h60
  text "1MIL" at 12894.46,3515.64 h60
  text "OTHER" at 13391.46,3515.64 h60
  text "BOARD FINISH:" at 11332.46,3356.64 h60
  text "SILKSCREEN:" at 11487.68,3238.64 h60
  text "X" at 12436.46,3238.64 h60
  text "TOP" at 12562.46,3238.64 h60
  text "BOTTOM" at 13073.46,3238.64 h60
  text "SILKSCREEN COLOR:" at 11487.68,3071.64 h60
  text "X" at 12435.42,3071.64 h60
  text "WHITE" at 12562.46,3071.64 h60
  text "OTHER" at 13073.46,3071.64 h60
  text "SOLDER RESIST COLOR:" at 11487.68,2901.64 h60
  text "X" at 12055.42,2742.44 h60
  text "GREEN" at 12182.46,2742.44 h60
  text "BLUE" at 12773.46,2742.44 h60
  text "OTHER" at 13311.46,2742.44 h60
  text "IMMERSION GOLD (ENIG)" at 12393.46,2553.92 h60
  text "ENEPIG" at 13731,2550.64 h60
  text "SURFACE FINISH:" at 11332.46,2549.64 h60
  text "X" at 12206.51,2549.64 h60
  text "IMM. TIN/SILVER OR EQUIV" at 11662,2392.64 h60
  text "OTHER" at 13093.46,2392.64 h60
  text "ARRAY/PANEL:" at 11332.46,2213.64 h60
  text "CUT AND TRIM PER MECH LAYER 1" at 12393.46,2209.35 h60
  text "N.C. ROUTE" at 12393.46,2057.64 h60
  text "X" at 13072.46,2057.64 h60
  text "V. SCORE" at 13259.46,2057.64 h60
  text "CERTIFICATION:" at 11332.46,1920.64 h60
  text "MATERIALS AND WORKMANSHIP FOR ALL PCBS" at 12057.46,1920.64 h60
  text "TO MEET OR EXCEED THE REQUIREMENTS OF:" at 12057.46,1822.64 h60
  text "X" at 11683.96,1686.13 h60
  text "ANSI IPC-A-600F CLASS ->" at 11822.96,1686.13 h60
  text "X" at 13462.02,1686.13 h60
  text "2" at 13580.96,1686.14 h60
  text "1" at 13265.96,1684.64 h60
  text "3" at 13934.96,1684.64 h60
  text "X" at 11686.02,1526.64 h60
  text "UL 94V-0" at 11822.96,1526.64 h60
  text "X" at 12498.02,1526.64 h60
  text "RoHS" at 12634.96,1526.64 h60
  text "OTHER" at 13279.36,1526.64 h60
  text "PER ORDER" at 13676.42,1526.64 h60
  text "ADDITIONAL REQUIREMENTS:" at 11332.46,1385.64 h60
  text "MICROSECTION:" at 11407.23,1270.64 h60
  text "YES" at 12312.96,1270.64 h60
  text "REQUIRED" at 13174.46,1114.49 h60
  text "BARE BOARD ELEC. TEST:" at 11407.23,1111.64 h60
  text "NONE" at 12712.96,1111.64 h60
  text "X" at 13047.46,1111.64 h60
  text "PER ORDER" at 13766.46,1111.64 h60
  text "MANUFACTURER'S UL:" at 11407.23,954.64 h60
  text "RAIL" at 12572.96,950.35 h60
  text "METAL" at 13064.77,950.35 h60
  text "X" at 13440,950 h60
  text "SILK" at 13576.46,950.35 h60
  text ".Layer_Name" at 577,-858.49 h60
M11 Gerber Information:
  lines w10: -292,-930.17 6308,-930.17 ; -292,-726.83 6310,-726.83 ; -292,-523.5 -292,-1133.5 3713,-1133.5 6310,-1133.5 6310,-523.5 -291.5,-523.5 -291.5,-1133.5 1284,-1133.5 ; 2173,-1133.5 2173,-523.5 ; 3440,-726.83 3440,-523.5 ; 4280,-726.83 4280,-523.5 ; 4902,-1140 4902,-937.17
  text "ALL ARTWORK VIEWED FROM TOP SIDE" at -228.5,-655.67 h60
  text "BOARD #:" at 2248,-655.67 h60
  text ".PRJ_Number" at 2793.5,-655.67 h60
  text "REV:" at 3638,-655.67 h60
  text ".PCB_Rev" at 3929.5,-655.67 h60
  text "SVN REV:" at 4476,-655.67 h60
  text ".VersionControl_RevNumber" at 4982,-655.67 h60
  text "LAYER NAME =" at -228.5,-858.49 h60
  text "TID #:" at 2248,-879 h60
  text ".TID" at 2793.5,-879 h60
  text "PLOT NAME =" at -228.5,-1064.34 h60
  text ".plot_File_Name" at 577,-1064.34 h60
  text "GENERATED    :" at 2250,-1064.34 h60
  text ".Print_Date" at 3119.5,-1064.34 h60
  text ".Print_Time" at 3848.5,-1064.34 h60
  text "TEXAS INSTRUMENTS" at 5113,-1064.34 h60
M12 Stackup:
  drawing of 295 lines, arcs and shapes, not listed
  text "Layer" at 9540,7685 h60
  text "Name" at 9949.91,7685 h60
  text "Material" at 10889.65,7685 h60
  text "Thickness" at 11749.42,7685 h60
  text "Constant" at 12399.26,7685 h60
  text "Board Layer Stack" at 12969.12,7685 h60
  text "1" at 9540,7565 h60
  text "Top Overlay" at 9949.91,7565 h60
  text "2" at 9540,7445 h60
  text "Top Solder" at 9949.91,7445 h60
  text "Solder Resist" at 10889.65,7445 h60
  text "0.40mil" at 11749.42,7445 h60
  text "3.5" at 12399.26,7445 h60
  text "3" at 9540,7325 h60
  text "Top Layer" at 9949.91,7325 h60
  text "Copper" at 10889.65,7325 h60
  text "1.40mil" at 11749.42,7325 h60
  text "4" at 9540,7205 h60
  text "Dielectric1" at 9949.91,7205 h60
  text "FR-4 High TG" at 10889.65,7205 h60
  text "10.00mil" at 11749.42,7205 h60
  text "4.2" at 12399.26,7205 h60
  text "5" at 9540,7085 h60
  text "Signal Layer 1" at 9949.91,7085 h60
  text "Copper" at 10889.65,7085 h60
  text "1.40mil" at 11749.42,7085 h60
  text "6" at 9540,6965 h60
  text "Dielectric 2" at 9949.91,6965 h60
  text "FR-4 High TG" at 10889.65,6965 h60
  text "27.00mil" at 11749.42,6965 h60
  text "4.2" at 12399.26,6965 h60
  text "7" at 9540,6845 h60
  text "Signal Layer 2" at 9949.91,6845 h60
  text "Copper" at 10889.65,6845 h60
  text "1.40mil" at 11749.42,6845 h60
  text "8" at 9540,6725 h60
  text "Dielectric 3" at 9949.91,6725 h60
  text "FR-4 High TG" at 10889.65,6725 h60
  text "10.00mil" at 11749.42,6725 h60
  text "4.2" at 12399.26,6725 h60
  text "9" at 9540,6605 h60
  text "Bottom Layer" at 9949.91,6605 h60
  text "Copper" at 10889.65,6605 h60
  text "1.40mil" at 11749.42,6605 h60
  text "10" at 9540,6485 h60
  text "Bottom Solder" at 9949.91,6485 h60
  text "Solder Resist" at 10889.65,6485 h60
  text "0.40mil" at 11749.42,6485 h60
  text "3.5" at 12399.26,6485 h60
  text "11" at 9540,6365 h60
  text "Bottom Overlay" at 9949.91,6365 h60
  text ".Layer_Name" at 577,-858.49 h60
M13 Component Bodies Top:
  text ".Layer_Name" at 577,-858.49 h60
M14 Component Bodies Bottom:
  text ".Layer_Name" at 577,-858.49 h60
M15 Courtyards Top:
  text ".Layer_Name" at 577,-858.49 h60
M16 Courtyards Bottom:
  text ".Layer_Name" at 577,-858.49 h60
Drill Drawing:
  circle w10: c6363.82,3620.27 r24.92
  circle w10: c6363.82,2424.27 r14.95
  circle w10: c6363.82,2424.27 r24.92
  lines w10: 6338.91,2249.85 6388.74,2249.85 6388.74,2299.68 6338.91,2299.68 6338.91,2249.85 ; 6338.91,2573.77 6363.82,2548.85 6388.74,2573.77 6363.82,2598.68 6338.91,2573.77 ; 6338.91,2698.35 6338.91,2710.81 6351.37,2723.27 6338.91,2735.72 6338.91,2748.18 6351.37,2748.18 6363.82,2735.72 6376.28,2748.18 6388.74,2748.18 6388.74,2735.72 6376.28,2723.27 6388.74,2710.81 6388.74,2698.35 6376.28,2698.35 6363.82,2710.81 6351.37,2698.35 6338.91,2698.35 ; 6338.91,2860.31 6351.37,2860.31 6363.82,2847.85 6376.28,2860.31 6388.74,2860.31 6376.28,2872.77 6388.74,2885.22 6376.28,2885.22 6363.82,2897.68 6351.37,2885.22 6338.91,2885.22 6351.37,2872.77 6338.91,2860.31 ; 6338.91,3047.18 6388.74,3047.18 6363.82,2997.35 6338.91,3047.18 ; 6338.91,3146.85 6388.74,3146.85 6388.74,3196.68 6338.91,3196.68 6338.91,3146.85 ; 6338.91,3308.81 6351.37,3308.81 6363.82,3296.35 6376.28,3308.81 6388.74,3308.81 6376.28,3321.27 6388.74,3333.72 6376.28,3333.72 6363.82,3346.18 6351.37,3333.72 6338.91,3333.72 6351.37,3321.27 6338.91,3308.81 ; 6338.91,3445.85 6363.82,3458.31 6388.74,3445.85 6376.28,3470.77 6388.74,3495.68 6363.82,3483.22 6338.91,3495.68 6351.37,3470.77 6338.91,3445.85 ; 6338.91,3794.68 6388.74,3794.68 6363.82,3744.85 6338.91,3794.68 ; 6348.88,2865.29 6356.35,2865.29 6363.82,2857.82 6371.3,2865.29 6378.77,2865.29 6371.3,2872.77 6378.77,2880.24 6371.3,2880.24 6363.82,2887.72 6356.35,2880.24 6348.88,2880.24 6356.35,2872.77 6348.88,2865.29 ; 6348.88,3156.82 6378.77,3156.82 6378.77,3186.72 6348.88,3186.72 6348.88,3156.82 ; 6348.88,3784.72 6378.77,3784.72 6363.82,3754.82 6348.88,3784.72
  lines w12: 6271,2205 8389.44,2205 ; 6271,3849.5 8389.44,3849.5 ; 6641.51,2055.5 6641.51,3999 ; 6998.67,2055.5 6998.67,3999 ; 7660.15,2055.5 7660.15,3999 ; 7944.35,2055.5 7944.35,3999 ; 6271,2055.5 8389.44,2055.5 8389.44,3999 6271,3999 6271,2055.5
  text "Symbol" at 6360.7,3894.35 h72
  text "Quantity" at 6686.36,3894.35 h72
  text "Finished Hole Size" at 7043.52,3894.35 h72
  text "Plated" at 7705,3894.35 h72
  text "Hole Type" at 7989.2,3894.35 h72
  text "6" at 6686.36,3744.85 h60
  text "43.31mil (1.100mm)" at 7043.52,3744.85 h60
  text "NPTH" at 7705,3744.85 h60
  text "Round" at 7989.2,3744.85 h60
  text "41" at 6686.36,3595.35 h60
  text "7.87mil (0.200mm)" at 7043.52,3595.35 h60
  text "PTH" at 7705,3595.35 h60
  text "Round" at 7989.2,3595.35 h60
  text "233" at 6686.36,3445.85 h60
  text "8.00mil (0.203mm)" at 7043.52,3445.85 h60
  text "PTH" at 7705,3445.85 h60
  text "Round" at 7989.2,3445.85 h60
  text "277" at 6686.36,3296.35 h60
  text "10.00mil (0.254mm)" at 7043.52,3296.35 h60
  text "PTH" at 7705,3296.35 h60
  text "Round" at 7989.2,3296.35 h60
  text "2" at 6686.36,3146.85 h60
  text "33.46mil (0.850mm)" at 7043.52,3146.85 h60
  text "PTH" at 7705,3146.85 h60
  text "Round" at 7989.2,3146.85 h60
  text "31" at 6686.36,2997.35 h60
  text "40.00mil (1.016mm)" at 7043.52,2997.35 h60
  text "PTH" at 7705,2997.35 h60
  text "Round" at 7989.2,2997.35 h60
  text "8" at 6686.36,2847.85 h60
  text "43.31mil (1.100mm)" at 7043.52,2847.85 h60
  text "PTH" at 7705,2847.85 h60
  text "Round" at 7989.2,2847.85 h60
  text "1" at 6686.36,2698.35 h60
  text "59.06mil (1.500mm)" at 7043.52,2698.35 h60
  text "PTH" at 7705,2698.35 h60
  text "Round" at 7989.2,2698.35 h60
  text "4" at 6686.36,2548.85 h60
  text "62.99mil (1.600mm)" at 7043.52,2548.85 h60
  text "PTH" at 7705,2548.85 h60
  text "Round" at 7989.2,2548.85 h60
  text "5" at 6686.36,2399.35 h60
  text "63.00mil (1.600mm)" at 7043.52,2399.35 h60
  text "PTH" at 7705,2399.35 h60
  text "Round" at 7989.2,2399.35 h60
  text "4" at 6686.36,2249.85 h60
  text "125.98mil (3.200mm)" at 7043.52,2249.85 h60
  text "PTH" at 7705,2249.85 h60
  text "Round" at 7989.2,2249.85 h60
  text "612 Total" at 6686.36,2100.35 h60
  text ".Layer_Name" at 577,-858.49 h60

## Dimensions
0,0 to 4100,0 on M2 Board Dimensions
0,0 to 0,3450 on M2 Board Dimensions
0,-400 to 1000,-400 on M2 Board Dimensions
